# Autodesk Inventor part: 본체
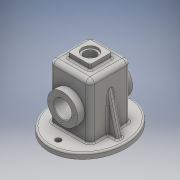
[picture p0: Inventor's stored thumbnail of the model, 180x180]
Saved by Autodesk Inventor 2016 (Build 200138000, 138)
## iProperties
Created: 2017-07
Part Number: 본체
Material: 일반
Document SubType Name: Modeling
Designer: USER
Density: 1 g/cm^3
Appearance: 기본값
Author: USER
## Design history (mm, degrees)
sketch "스케치1"
  geometry: L1 (0, 0)-(74, 0); L2 (74, 0)-(74, 100); L3 (74, 100)-(0, 100); L4 (0, 100)-(0, 0)
  constraints: 8 end point, 2 parallel, 1 horizontal, 1 perpendicular
  dimensions: "d0" = 74 distance between parallel lines of L2 L4; "d1" = 100 distance between parallel lines of L1 L3
extrude "돌출1" new body sketch "스케치1" stored distance "d2" = 74; taper "d3" = 0 deg
node "작업 평면1"
sketch "스케치2"
  geometry: L1 (17, 17)-(57, 17); L2 (57, 17)-(57, 57); L3 (57, 57)-(17, 57); L4 (17, 57)-(17, 17); L5 (0, 74)-(74, 74) reference; L6 (74, 74)-(74, 0) reference; 4 further points
  constraints: 8 end point, 3 midpoint, 2 parallel, 1 horizontal, 1 horizontal alignment, 1 perpendicular, 1 vertical alignment
  dimensions: "d5" = 40 distance between parallel lines of L2 L4; "d6" = 40 distance between parallel lines of L1 L3
extrude "돌출2" join sketch "스케치2" stored distance "d8" = 74; taper "d9" = 0 deg
sketch "스케치3"
  geometry: L1 (37, -37)-(-28, -37); L2 (37, -37)-(37, 38); L3 (0, -74)-(74, -74) reference; L4 (0, -74)-(0, 0) reference; 4 further points; 1 other entity
  constraints: 4 end point, 2 midpoint, 2 vertical, 1 coincident, 1 horizontal, 1 horizontal alignment, 1 vertical alignment, 4 other
  dimensions: "d10" = 65 distance of L1.start L1.end; "d11" = 75 distance of L1.start L2.end
extrude "돌출3" join sketch "스케치3" distance "d12" = 10; taper "d13" = 0 deg
sketch "스케치4"
  geometry: L1 (102, 110)-(-28, 110) reference; C1 r 27.5 at (37, 55); 2 further points
  constraints: 1 centre point, 1 midpoint, 1 vertical alignment
  dimensions: "d14" = 55 diameter of C1; "d15" = 55 distance from line of L1 C1.centre
extrude "돌출4" join sketch "스케치4" distance "d16" = 13; taper "d17" = 0 deg
sketch "스케치5"
  geometry: C1 r 27.5 at (37, -55) reference; C2 r 27.5 at (37, -55); 1 further point
  constraints: 1 centre point, 1 coincident
  dimensions: "d18" = 55 diameter of C2
extrude "돌출5" join sketch "스케치5" distance "d19" = 13; taper "d20" = 0 deg
node "작업 평면2"
sketch "스케치6"
  geometry: L1 (74, 100)-(0, 100) reference; L2 (74, 0)-(74, 100) reference; L3 (0, 100)-(0, 0) reference; L4 (-38, -10)-(112, -10) reference; L5 (112, 0)-(-38, 0) reference; L6 (69, -10)-(5, -10); L7 (87, 17.5)-(87, 72.5) reference; L8 (-13, 72.5)-(-13, 17.5) reference; L9 (5, -10)-(5, 95); L10 (5, 95)-(69, 95); L11 (69, 95)-(69, -10); 1 further point
  constraints: 8 end point, 2 point on line
  dimensions: "d76" = 5 distance between parallel lines of L10 L1; "d77" = 5 distance between parallel lines of L9 L3; "d78" = 5 distance between parallel lines of L2 L11
extrude "돌출6" cut sketch "스케치6" stored distance "d41" = 64; taper "d42" = 0 deg
sketch "스케치9"
  geometry: L1 (74, 74)-(74, 0) reference; C1 r 14 at (37, 37); 2 further points
  constraints: 1 centre point, 1 horizontal alignment, 1 midpoint, 1 vertical alignment
  dimensions: "d49" = 28 diameter of C1
extrude "돌출9" cut sketch "스케치9" distance "d50" = 4; taper "d51" = 0 deg
sketch "스케치10"
  geometry: C1 r 14 at (0, 0) reference; C2 r 10.5 at (0, 0); 1 further point
  constraints: 1 centre point, 1 coincident
  dimensions: "d52" = 21 diameter of C2
extrude "돌출10" cut sketch "스케치10" stored distance "d53" = 4; taper "d54" = 0 deg
sketch "스케치11" dims "d55" = 45
  geometry: C1 r 27.5 at (0, 0) reference; 3 further points
  constraints: 1 coincident, 1 vertical alignment, 2 other
hole "구멍1" sketch "스케치11" at (0, -22.5) diameter "d56" = 3.242; stored, may be unused: countersink angle "d60" = 90 deg, drill point angle "d62" = 118 deg; dims "d57" = 8, "d58" = 4, "d59" = 2, "d61" = 10
node "작업 평면3"
sketch "스케치12"
  geometry: L1 (-23, -37)-(-37, -37); C1 r 5 at (-37, 21); C2 r 5 at (-37, -95); 1 further point
  constraints: 2 centre point, 2 end point, 2 vertical alignment, 1 horizontal, 1 horizontal alignment, 1 other
  dimensions: "d67" = 10 diameter of C1; "d68" = 10 diameter of C2; "d69" = 116 distance of C2.centre C1.centre; "d70" = 58 distance of C1.centre L1.end
extrude "돌출11" cut sketch "스케치12" stored distance "d71" = 4; taper "d72" = 0 deg
fillet "모깎기1" dims "d73" = 8
sketch "스케치14"
  geometry: C1 r 27.5 at (32, -55) reference; C2 r 27.5 at (32, -55); 1 further point
  constraints: 1 centre point, 1 coincident
  dimensions: "d79" = 55 diameter of C2
extrude "돌출12" join sketch "스케치14" distance "d80" = 7; taper "d81" = -45 deg
sketch "스케치15"
  geometry: C1 r 27.5 at (32, -50) reference; C2 r 27.5 at (32, -50); 1 further point
  constraints: 1 centre point, 1 coincident
  dimensions: "d82" = 55 diameter of C2
extrude "돌출13" join sketch "스케치15" distance "d83" = 7; taper "d84" = -45 deg
sketch "스케치16"
  geometry: C1 r 27.5 at (0, 0) reference; C2 r 16 at (0, 0); 1 further point
  constraints: 1 centre point, 1 coincident
  dimensions: "d85" = 32 diameter of C2
extrude "돌출14" cut sketch "스케치16" stored distance "d86" = 7; taper "d87" = 0 deg
fillet "모깎기2" dims "d91" = 3
fillet "모깎기3" dims "d92" = 3
chamfer "모따기1" distance "d93" = 1; stored, may be unused: second distance "d94" = 2, angle "d95" = 45 deg
fillet "모깎기4" dims "d96" = 3
fillet "모깎기5" dims "d97" = 0.5
fillet "모깎기6" dims "d98" = 3
fillet "모깎기7" dims "d99" = 0.5
node "작업 평면5"
sketch "스케치17"
  geometry: L1 (-37, 3)-(-37, 92) reference; L2 (37, 92)-(37, 3) reference; L3 (-37, 72.194)-(-55, 0); L4 (37, 72.194)-(55, 0); L5 (-65, -10)-(65, -10) reference; L6 (-65, -10)-(-65, 44.039); L7 (65, -10)-(65, 47.5); L8 (-37, 72.194)-(-37, 0); L9 (-29, 0)-(-40, 0) reference; L10 (37, 72.194)-(37, 37); L11 (-55, 0)-(-37, 0); L12 (37, 37)-(55, 0); 3 further points; 1 other entity
  constraints: 16 end point, 4 point on line, 3 vertical, 1 collinear, 2 other
  dimensions: "d101" = 14 deg angle of L7 L4; "d102" = 14 deg angle of L6 L3; "d103" = 10 distance from line of L6 L3.end; "d104" = 10 distance from line of L7 L4.end; "d105" = 55 distance of L4.end point (0, 0)
extrude "돌출15" join sketch "스케치17" stored distance "d106" = 10; taper "d107" = 0 deg
node "작업 평면6"
fillet "모깎기8" dims "d109" = 3
sketch "스케치18"
  geometry: L1 (46, -18)-(12, -18) reference; L2 (66, 0)-(66, 89) reference; 2 further points
  constraints: 1 other
  dimensions: "d110" = 30 distance from line of L1 point (29, 12); "d111" = 37 distance from line of L2 point (29, 12)
feature "엠보싱1" sketch "스케치18" dims "d112" = 0.5, "d113" = 0
node "솔리드1"
mirror "대칭1"
pattern_circular "원형 패턴2" dims angle "d89" = 360 deg
mirror "대칭2"
other parameters: "d21" = 0, "d66" = -37, "d100" = 37, "d108" = 0
